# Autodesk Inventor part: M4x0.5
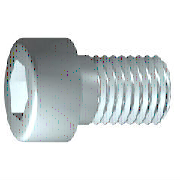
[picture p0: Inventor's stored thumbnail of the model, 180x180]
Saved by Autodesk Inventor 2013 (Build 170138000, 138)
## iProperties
IsCustomPart: 1
Company: 한국ATC센터
Created: 2014-10
Part Number: M4x0.5
Material: 강철, 연강
Description: 6각머리 태핑 나사
Document SubType Name: Modeling
Standard: KS B 1003
Designer: 한국ATC센터
Standards Organization: KS
Language: ko-KR
Size Designation: M 4 x 16
Categories: <MemberInstance><Categories><Category DisplayName="조임쇠" InternalName="e4da775c-781d-43d5-af7c-5136215cf5a6" Mnemonic="FSTN"><Category DisplayName="볼트" InternalN
Density: 7.86 g/cm^3
Mass: 2.62973 g
Surface Area: 3.81119 cm^2
Volume: 0.334572 cm^3
Author: KYOUNG IL JANG
Revision Number: 1
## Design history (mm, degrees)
sketch "스케치1"
  geometry: L1 (-1, 0)-(16, 0); L2 (16, 0)-(16, 2); L3 (16, 2)-(1.75, 2); L4 (1.75, 2)-(1.32, 2); L5 (1.32, 2)-(0, 2); L6 (0, 2)-(0, 3.5); L7 (0, 3.5)-(-4, 3.5); L8 (-4, 3.5)-(-4, 1.732); L9 (-4, 1.732)-(-2, 1.732); L10 (-2, 1.732)-(-1, 0); L11 (-8, 0)-(20, 0) reference; L12 (0, -0.7)-(0, 4.2) reference; L13 (1.75, 2)-(0, 2)
  constraints: 22 end point, 6 parallel, 2 collinear, 2 perpendicular, 1 horizontal, 1 point on line
  dimensions: "d1" = 14.25 distance from line of L3.end L2 (= GEL); "d2" = 0.42952 distance of L4.end L3.end (computed from GAL); "d3" = 4 distance between parallel lines of L8 L6 (= KOH); "d4" = 2 distance of L8.end L9.end (= INTI); "d5" = 60 deg angle of L10 L1; "d6" = 4 diameter of L3 L1 (= GD); "d7" = 4 diameter of L5 L1 (= BDM); "d8" = 3.4641 diameter of L9 L1 (= 1.1547 x SW); "d9" = 7 diameter of L7 L1 (= KOD); "d26" = 16 distance between parallel lines of L12 L2 (= NLG)
revolve "본체" sketch "스케치1" stored, may be unused: angle "d10" = 90 deg
sketch "스케치2"
  geometry: L1 (0, -4.9)-(0, 4.9) reference; L2 (-4.9, 0)-(4.9, 0) reference; L3 (1.732, 0)-(0.866, -1.5); L4 (0.866, -1.5)-(-0.866, -1.5); L5 (-0.866, -1.5)-(-1.732, 0); L6 (-1.732, 0)-(-0.866, 1.5); L7 (-0.866, 1.5)-(0.866, 1.5); L8 (0.866, 1.5)-(1.732, 0); 2 further points
  constraints: 12 end point, 1 coincident, 1 horizontal alignment, 1 point on line, 12 other
extrude "슬롯" join sketch "스케치2" stored distance "d11" = 10; taper "d12" = 0 deg
workplane "Work Plane1"
fillet "Fillet2" dims "d30" = 0.1 (= R)
body "Solid1"
fillet "모깎기1" dims "d17" = 0.4 (= RR)
feature "스레드" dims "d13" = 14.25 (= GEL), "d14" = 0
chamfer "모따기1" distance "d15" = 0.42941 (= -0.5 x SPD + 0.5 x GD); stored, may be unused: second distance "d16" = 0.42941 (= GUL), angle "d27" = 45 deg
other parameters: "GD" = 4 (= NND) [user parameter; used in 2 equation terms], "NLG" = 16 [user parameter; used in 1 equation term], "GEL" = 14.25 [user parameter; used in 2 equation terms], "KOD" = 7 [user parameter; used in 1 equation term], "KOH" = 4 [user parameter; used in 1 equation term], "INTI" = 2 [user parameter; used in 1 equation term], "GAL" = 0.42941 (= 0.61345 x PTC) [user parameter; used in 1 equation term], "GUL" = 0.42941 (= 0.61345 x PTC) [user parameter; used in 1 equation term], "BDM" = 4 (= NND) [user parameter; used in 1 equation term], "SW" = 3 [user parameter; used in 2 equation terms], "RR" = 0.4 [user parameter; used in 1 equation term], "SPD" = 3.14117 (= NND - 1.2269 x PTC) [user parameter; used in 1 equation term], "d19" = 0, "d28" = 0, "d29" = 0, "R" = 0.1 [user parameter; used in 1 equation term], "PHH" = 0.2 [user parameter], "GD1" = 3.14117 (= THREADDIA - 1.2269 x PTC) [user parameter], "THREADDIA" = 4 [user parameter; used in 1 equation term], "FAWI" = 45 deg [user parameter], "TPU" = 14.28571 (computed from PTC) [user parameter], "PTC" = 0.7 [user parameter; used in 5 equation terms], "NND" = 4 [user parameter; used in 3 equation terms], "TOA" = 30 deg [user parameter], "E0" = 3.465 (= 1.155 x SW) [user parameter]
